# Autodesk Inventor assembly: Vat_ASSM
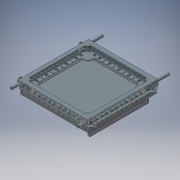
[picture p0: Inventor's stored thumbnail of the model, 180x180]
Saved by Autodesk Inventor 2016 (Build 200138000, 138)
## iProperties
Created: 2015-11
Part Number: Vat_ASSM
Document SubType Name: Assembly
Designer: John
Author: John
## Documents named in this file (4)
- D:\3D Printer Designs\John Ledden Designs\DLP Printer\V0-4\Vat_ASSM.iam
- D:\3D Printer Designs\John Ledden Designs\DLP Printer\V0-4\Vat_MountingPlate.ipt
- D:\3D Printer Designs\John Ledden Designs\DLP Printer\V0-4\M8_Rod_275mm.ipt
- D:\3D Printer Designs\John Ledden Designs\DLP Printer\V0-4\FlexVat_ASSM.iam
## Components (4 placed, 4 different names)
1. Vat_MountingPlate_1083
2. M8_Rod_275mm_1084
3. M8_Rod_275mm_1085
4. FlexVat_ASSM_1086 [sub-assembly]
